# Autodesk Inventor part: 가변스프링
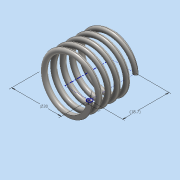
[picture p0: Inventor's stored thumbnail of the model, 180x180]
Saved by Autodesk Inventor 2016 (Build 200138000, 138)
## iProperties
Created: 2019-01
Part Number: 가변스프링
Material: 스테인레스 스틸
Document SubType Name: Modeling
Designer: 3sil_cad018
Density: 8 g/cm^3
Appearance: 반연마
Mass: 7.7167 g
Surface Area: 19.6433 cm^2
Volume: 0.964587 cm^3
Author: 3sil_cad018
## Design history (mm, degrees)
sketch "스케치1"
  geometry: L1 (0, 0)-(10, 0); L2 (10, 0)-(10, 18.7); L3 (10, 18.7)-(0, 18.7); L4 (0, 18.7)-(0, 0); C1 r 1 at (10, 0)
  constraints: 8 end point, 2 parallel, 1 centre point, 1 coincident, 1 horizontal, 1 perpendicular
  dimensions: "d0" = 20 diameter of L2 L4; "d1" = 18.7 distance of L1.end L2.end (derived); "d2" = 2 diameter of C1
feature "코일1" pitch "d3" = 10; turns "d5" = 5; dims "d4" = 18.7 (= d1), "d6" = 0, angle "d7" = 90 deg, angle "d8" = 90 deg, "d9" = 0, "d10" = 0
sketch "스케치2"
  geometry: L1 (-11, 0)-(-9, 0) reference; 1 further point
  constraints: 1 horizontal alignment
extrude "돌출1" cut sketch "스케치2" stored distance "d11" = 10; taper "d12" = 0 deg
node "작업 평면1"
sketch "스케치3"
  geometry: L1 (1, 0)-(-1, 0) reference; 1 further point
  constraints: 1 horizontal alignment
extrude "돌출2" cut sketch "스케치3" stored distance "d14" = 10; taper "d15" = 0 deg
node "솔리드1"
node "절단 모서리 투영1"
node "절단 모서리 투영2"
other parameters: "d13" = 90 deg
